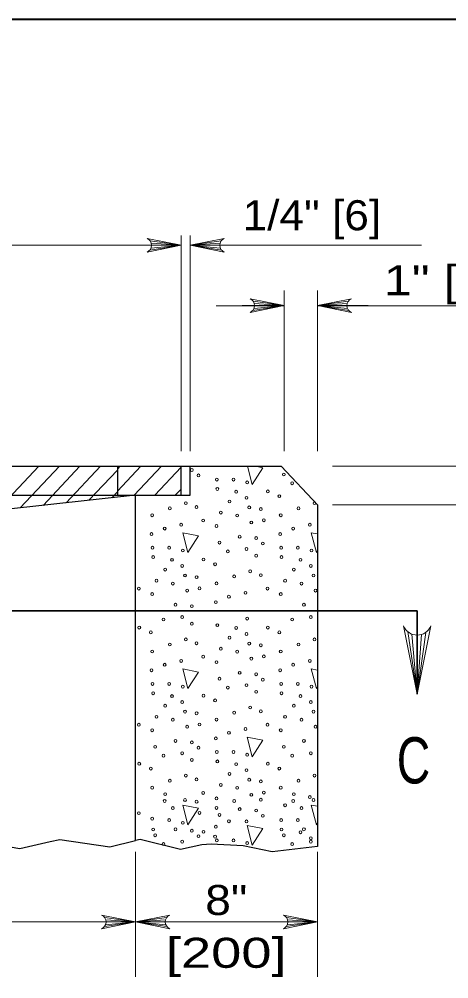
# Model space of a CAD drawing. Extents: x -410.5 to -376.5, y 1617.6 to 1661.6.
# Drawn here: x -402.283 to -400.052, y 1634.082 to 1639.062 of the extents above; entities that cross this region are included whole.
import ezdxf
from ezdxf.enums import TextEntityAlignment as Align

# ---------------------------------------------------------------- set-up
doc = ezdxf.new("R2010")
doc.units = 0
doc.header["$LTSCALE"] = 0.062
doc.layers.add('1', color=7, linetype='Continuous', lineweight=13)

msp = doc.modelspace()

# ---------------------------------------------------------------- linework, layer by layer
at = {"layer": '1', "lineweight": 25}
for p, q in [((-408.45475, 1639.06183), (-376.95475, 1639.06183)), ((-401.77275, 1636.74175), (-401.39508, 1636.74175)), ((-401.44233, 1636.59183), (-401.44233, 1636.74175)), ((-404.3215, 1636.59183), (-401.77275, 1636.59183)), ((-401.67833, 1634.79958), (-401.67833, 1636.59183))]:
    msp.add_line(p, q, dxfattribs=at)
at = {"layer": '1'}
for p, q in [((-401.44233, 1636.82042), (-401.44233, 1637.93875)), ((-401.39508, 1636.82042), (-401.39508, 1637.93875)), ((-401.60442, 1637.864), (-401.44233, 1637.88875)), ((-401.60258, 1637.91117), (-401.44233, 1637.88875)), ((-401.59833, 1637.87442), (-401.44233, 1637.88875)), ((-401.59717, 1637.90008), (-401.44233, 1637.88875)), ((-401.5955, 1637.88875), (-401.44233, 1637.88875)), ((-401.23483, 1637.91117), (-401.39508, 1637.88875)), ((-401.24033, 1637.90008), (-401.39508, 1637.88875)), ((-401.39508, 1637.88875), (-400.19475, 1637.88875)), ((-401.24192, 1637.88875), (-401.39508, 1637.88875)), ((-401.23908, 1637.87442), (-401.39508, 1637.88875)), ((-401.233, 1637.864), (-401.39508, 1637.88875)), ((-400.90758, 1636.82042), (-400.90758, 1637.65358)), ((-400.73433, 1636.82042), (-400.73433, 1637.65358)), ((-400.90758, 1637.57492), (-401.26067, 1637.57492)), ((-400.90758, 1637.57567), (-401.12608, 1637.57567)), ((-401.06975, 1637.55092), (-400.90758, 1637.57567)), ((-401.06783, 1637.59808), (-400.90758, 1637.57567)), ((-401.06358, 1637.56133), (-400.90758, 1637.57567)), ((-401.06242, 1637.587), (-400.90758, 1637.57567)), ((-401.06075, 1637.57567), (-400.90758, 1637.57567)), ((-400.57408, 1637.59808), (-400.73433, 1637.57567)), ((-400.5795, 1637.587), (-400.73433, 1637.57567)), ((-400.73433, 1637.57567), (-400.47133, 1637.57567)), ((-400.58117, 1637.57567), (-400.73433, 1637.57567)), ((-400.57833, 1637.56133), (-400.73433, 1637.57567)), ((-400.57217, 1637.55092), (-400.73433, 1637.57567)), ((-399.40992, 1637.57492), (-400.73433, 1637.57492)), ((-402.39733, 1636.513), (-402.18125, 1636.74175)), ((-402.27817, 1636.52608), (-402.0745, 1636.74175)), ((-402.15908, 1636.53908), (-401.96767, 1636.74175)), ((-402.03983, 1636.55217), (-401.86083, 1636.74175)), ((-401.89075, 1636.74175), (-401.70192, 1636.74175)), ((-401.77275, 1636.61325), (-401.65133, 1636.74167)), ((-401.77275, 1636.72625), (-401.75817, 1636.74167)), ((-401.686, 1636.59192), (-401.54458, 1636.74167)), ((-401.57925, 1636.59192), (-401.44233, 1636.73683)), ((-401.39508, 1636.59183), (-401.39508, 1636.74175)), ((-401.01817, 1636.7345), (-401.05558, 1636.74175)), ((-400.65567, 1636.74175), (-394.85592, 1636.74175)), ((-401.92075, 1636.56525), (-401.77275, 1636.722)), ((-401.80167, 1636.57825), (-401.77275, 1636.60892)), ((-401.74208, 1636.58483), (-401.73542, 1636.59183)), ((-401.6825, 1636.59133), (-401.68208, 1636.59183)), ((-401.47242, 1636.59192), (-401.44233, 1636.62375)), ((-400.65567, 1636.54183), (-400.27733, 1636.54183)), ((-400.65567, 1636.54183), (-394.85592, 1636.54183)), ((-400.73433, 1636.39075), (-400.76633, 1636.39708)), ((-400.26583, 1635.88375), (-400.21625, 1635.5595)), ((-400.24508, 1635.8715), (-400.21625, 1635.5595)), ((-400.17142, 1635.88), (-400.21625, 1635.5595)), ((-400.19358, 1635.86908), (-400.21625, 1635.5595)), ((-400.21625, 1635.86583), (-400.21625, 1635.5595)), ((-400.73442, 1635.68408), (-400.76633, 1635.69033)), ((-400.73433, 1634.9775), (-400.76633, 1634.98367)), ((-401.67833, 1634.09325), (-401.67833, 1634.74117)), ((-400.73433, 1634.09325), (-400.73433, 1634.74117)), ((-401.83858, 1634.40017), (-401.67833, 1634.37775)), ((-401.83317, 1634.38908), (-401.67833, 1634.37775)), ((-401.51808, 1634.40017), (-401.67833, 1634.37775)), ((-401.5235, 1634.38908), (-401.67833, 1634.37775)), ((-400.89458, 1634.40017), (-400.73433, 1634.37775)), ((-400.88917, 1634.38908), (-400.73433, 1634.37775)), ((-402.5235, 1634.37775), (-401.67833, 1634.37775)), ((-401.84042, 1634.353), (-401.67833, 1634.37775)), ((-401.83433, 1634.36333), (-401.67833, 1634.37775)), ((-401.8315, 1634.37775), (-401.67833, 1634.37775)), ((-401.67833, 1634.37775), (-400.96875, 1634.37775)), ((-401.52517, 1634.37775), (-401.67833, 1634.37775)), ((-401.52233, 1634.36333), (-401.67833, 1634.37775)), ((-401.51617, 1634.353), (-401.67833, 1634.37775)), ((-401.02175, 1634.37775), (-400.73433, 1634.37775)), ((-400.89642, 1634.353), (-400.73433, 1634.37775)), ((-400.89033, 1634.36333), (-400.73433, 1634.37775)), ((-400.8875, 1634.37775), (-400.73433, 1634.37775))]:
    msp.add_line(p, q, dxfattribs=at)
at = {"layer": '1', "lineweight": 35}
for p, q in [((-405.888, 1635.99217), (-400.21625, 1635.99217)), ((-400.21625, 1635.99217), (-400.21625, 1635.5595))]:
    msp.add_line(p, q, dxfattribs=at)
at = {"layer": '1', "lineweight": 40}
msp.add_lwpolyline([(-408.45475, 1639.06183), (-376.95475, 1639.06183), (-376.95475, 1618.06183), (-408.45475, 1618.06183)], close=True, dxfattribs=at)
msp.add_lwpolyline([(-408.45475, 1639.06183), (-376.95475, 1639.06183), (-376.95475, 1618.06183), (-408.45475, 1618.06183)], close=True, dxfattribs=at)
at = {"layer": '1'}
for points in [[(-401.61933, 1637.85342), (-401.44233, 1637.88875), (-401.61933, 1637.92417)], [(-401.21808, 1637.85342), (-401.39508, 1637.88875), (-401.21808, 1637.92417)], [(-404.65192, 1637.88875), (-402.994, 1637.88875), (-401.86958, 1637.88875), (-401.44233, 1637.88875)], [(-401.08458, 1637.54033), (-400.90758, 1637.57567), (-401.08458, 1637.61108)], [(-400.55733, 1637.54033), (-400.73433, 1637.57567), (-400.55733, 1637.61108)], [(-401.09775, 1636.74167), (-401.07308, 1636.648), (-401.01817, 1636.7345)], [(-400.76633, 1636.39708), (-400.73933, 1636.29467), (-400.73425, 1636.3025)], [(-400.28708, 1635.9135), (-400.21625, 1635.5595), (-400.1455, 1635.9135)], [(-400.76633, 1635.69033), (-400.73933, 1635.588), (-400.73433, 1635.59583)], [(-400.76633, 1634.98367), (-400.73933, 1634.88117), (-400.73433, 1634.88925)], [(-401.85533, 1634.34233), (-401.67833, 1634.37775), (-401.85533, 1634.41317)], [(-401.50133, 1634.34233), (-401.67833, 1634.37775), (-401.50133, 1634.41317)], [(-400.91133, 1634.34233), (-400.73433, 1634.37775), (-400.91133, 1634.41317)]]:
    msp.add_lwpolyline(points, dxfattribs=at)
at = {"layer": '1', "lineweight": 25}
msp.add_lwpolyline([(-403.04708, 1636.44192), (-404.41592, 1636.59183), (-404.3215, 1636.59183), (-404.3215, 1636.74175), (-401.77275, 1636.74175), (-401.77275, 1636.59183), (-401.67833, 1636.59183)], close=True, dxfattribs=at)
for points in [[(-401.67833, 1636.59183), (-401.39508, 1636.59183), (-401.39508, 1636.74175), (-400.92308, 1636.74175), (-400.73433, 1636.54183), (-400.73433, 1634.76942)], [(-404.41592, 1634.78325), (-404.2725, 1634.75117), (-404.153, 1634.78225), (-403.98442, 1634.76358), (-403.92575, 1634.76642), (-403.82517, 1634.80067), (-403.76458, 1634.79342), (-403.7105, 1634.79125), (-403.49083, 1634.75217), (-403.33433, 1634.80033), (-403.13075, 1634.77958), (-402.962, 1634.81358), (-402.852, 1634.82042), (-402.67125, 1634.76517), (-402.5025, 1634.79617), (-402.27992, 1634.75808), (-402.12158, 1634.79417), (-402.07225, 1634.80517), (-401.81283, 1634.767), (-401.67833, 1634.79958)], [(-400.73433, 1634.76942), (-400.96875, 1634.74142), (-401.11925, 1634.77325), (-401.286, 1634.78183), (-401.33525, 1634.77683), (-401.44525, 1634.75283), (-401.65542, 1634.80508), (-401.67833, 1634.79958)]]:
    msp.add_lwpolyline(points, dxfattribs=at)
at = {"layer": '1'}
for points in [[(-401.43383, 1636.39708), (-401.40683, 1636.29467), (-401.35183, 1636.38108)], [(-401.43383, 1635.69033), (-401.40683, 1635.588), (-401.35183, 1635.67442)], [(-401.1, 1635.337), (-401.07308, 1635.23458), (-401.01817, 1635.321)], [(-401.43383, 1634.98367), (-401.40683, 1634.88117), (-401.35183, 1634.96767)], [(-401.1, 1634.87842), (-401.07308, 1634.77608), (-401.01817, 1634.86258)]]:
    msp.add_lwpolyline(points, close=True, dxfattribs=at)
for centre, radius, start, end in [((-401.63361, 1637.88882), 0.0382, 292.08605, 67.91218), ((-401.20382, 1637.88882), 0.0382, 112.08782, 247.91395), ((-401.09887, 1637.57573), 0.0382, 292.08605, 67.91218), ((-400.54302, 1637.57573), 0.0382, 112.08782, 247.91395), ((-400.2162, 1635.94207), 0.0764, 202.08605, 337.91218), ((-401.86961, 1634.3778), 0.0382, 292.08605, 67.91218), ((-401.48702, 1634.3778), 0.0382, 112.08782, 247.91395), ((-400.92561, 1634.3778), 0.0382, 292.08605, 67.91218)]:
    msp.add_arc(centre, radius, start, end, dxfattribs=at)
for centre, major_axis in [((-401.38687, 1636.72267), (0, 0.00756)), ((-401.35144, 1636.69469), (0, -0.00756)), ((-401.25682, 1636.67273), (0, -0.00756)), ((-401.17027, 1636.67273), (0, 0.00756)), ((-400.90894, 1636.69947), (0, 0.00756)), ((-401.25415, 1636.62408), (0, -0.00756)), ((-401.09912, 1636.65842), (0, -0.00756)), ((-400.86566, 1636.65365), (0, 0.00756)), ((-401.15586, 1636.60977), (0, 0.00756)), ((-401.10274, 1636.57827), (0, 0.00756)), ((-400.99188, 1636.61166), (0, -0.00756)), ((-400.93241, 1636.58686), (0, -0.00756)), ((-401.50046, 1636.52361), (0, -0.00756)), ((-401.41752, 1636.55029), (0, -0.00756)), ((-401.36257, 1636.53027), (0, -0.00756)), ((-401.19107, 1636.55919), (0, 0.00756)), ((-401.08827, 1636.52868), (0, 0.00756)), ((-400.83295, 1636.52361), (0, -0.00756)), ((-400.75001, 1636.55029), (0, -0.00756)), ((-401.59269, 1636.48757), (0, -0.00756)), ((-401.23641, 1636.50165), (0, 0.00756)), ((-401.15141, 1636.48669), (0, 0.00756)), ((-401.02792, 1636.52002), (0, -0.00756)), ((-400.92518, 1636.48757), (0, -0.00756)), ((-401.44189, 1636.43863), (0, -0.00756)), ((-401.32747, 1636.4606), (0, 0.00756)), ((-401.25893, 1636.43198), (0, 0.00756)), ((-401.07754, 1636.45041), (0, 0.00756)), ((-401.01262, 1636.4619), (0, -0.00756)), ((-400.77438, 1636.43863), (0, -0.00756)), ((-401.59597, 1636.38999), (0, -0.00756)), ((-401.52755, 1636.41861), (0, -0.00756)), ((-401.13817, 1636.37668), (0, 0.00756)), ((-400.92846, 1636.38999), (0, -0.00756)), ((-400.86004, 1636.41861), (0, -0.00756)), ((-401.24269, 1636.34612), (0, 0.00756)), ((-401.05312, 1636.36932), (0, 0.00756)), ((-401.01769, 1636.34135), (0, -0.00756)), ((-401.59058, 1636.31938), (0, -0.00756)), ((-401.50402, 1636.31938), (0, 0.00756)), ((-401.43288, 1636.30507), (0, -0.00756)), ((-401.19942, 1636.3003), (0, 0.00756)), ((-401.10302, 1636.31272), (0, 0.00756)), ((-401.05223, 1636.27804), (0, -0.00756)), ((-400.92307, 1636.31938), (0, -0.00756)), ((-400.83651, 1636.31938), (0, 0.00756)), ((-400.76537, 1636.30507), (0, -0.00756)), ((-401.58791, 1636.27073), (0, -0.00756)), ((-401.48961, 1636.25642), (0, 0.00756)), ((-401.43649, 1636.22492), (0, 0.00756)), ((-401.32563, 1636.25831), (0, -0.00756)), ((-401.26617, 1636.23351), (0, -0.00756)), ((-400.9204, 1636.27073), (0, -0.00756)), ((-400.82211, 1636.25642), (0, 0.00756)), ((-400.76898, 1636.22492), (0, 0.00756)), ((-401.52483, 1636.20584), (0, 0.00756)), ((-401.42203, 1636.17533), (0, 0.00756)), ((-401.08377, 1636.19694), (0, -0.00756)), ((-401.02881, 1636.17692), (0, -0.00756)), ((-400.85732, 1636.20584), (0, 0.00756)), ((-400.75452, 1636.17533), (0, 0.00756)), ((-401.57016, 1636.1483), (0, 0.00756)), ((-401.48516, 1636.13334), (0, 0.00756)), ((-401.36168, 1636.16667), (0, -0.00756)), ((-401.25893, 1636.13422), (0, -0.00756)), ((-401.16671, 1636.17026), (0, -0.00756)), ((-400.90265, 1636.1483), (0, 0.00756)), ((-400.81766, 1636.13334), (0, 0.00756)), ((-401.66122, 1636.10725), (0, 0.00756)), ((-401.59269, 1636.07863), (0, 0.00756)), ((-401.41129, 1636.09706), (0, 0.00756)), ((-401.34638, 1636.10855), (0, -0.00756)), ((-401.10813, 1636.08528), (0, -0.00756)), ((-400.99371, 1636.10725), (0, 0.00756)), ((-400.92518, 1636.07863), (0, 0.00756)), ((-400.74378, 1636.09706), (0, 0.00756)), ((-401.47193, 1636.02333), (0, 0.00756)), ((-401.26222, 1636.03664), (0, -0.00756)), ((-401.1938, 1636.06526), (0, -0.00756)), ((-400.80442, 1636.02333), (0, 0.00756)), ((-401.38687, 1636.01597), (0, 0.00756)), ((-401.53317, 1635.94695), (0, 0.00756)), ((-401.43677, 1635.95937), (0, 0.00756)), ((-401.38598, 1635.92469), (0, -0.00756)), ((-401.09912, 1635.95172), (0, -0.00756)), ((-400.86566, 1635.94695), (0, 0.00756)), ((-400.76926, 1635.95937), (0, 0.00756)), ((-401.65938, 1635.90496), (0, -0.00756)), ((-401.59992, 1635.88016), (0, -0.00756)), ((-401.25415, 1635.91738), (0, -0.00756)), ((-401.15586, 1635.90307), (0, 0.00756)), ((-400.99188, 1635.90496), (0, -0.00756)), ((-400.93241, 1635.88016), (0, -0.00756)), ((-401.41752, 1635.84359), (0, -0.00756)), ((-401.19107, 1635.85249), (0, 0.00756)), ((-401.10274, 1635.87157), (0, 0.00756)), ((-400.75001, 1635.84359), (0, -0.00756)), ((-401.59269, 1635.78087), (0, -0.00756)), ((-401.50046, 1635.81692), (0, -0.00756)), ((-401.36257, 1635.82357), (0, -0.00756)), ((-401.23641, 1635.79495), (0, 0.00756)), ((-401.15141, 1635.77999), (0, 0.00756)), ((-401.08827, 1635.82198), (0, 0.00756)), ((-401.02792, 1635.81332), (0, -0.00756)), ((-400.92518, 1635.78087), (0, -0.00756)), ((-400.83295, 1635.81692), (0, -0.00756)), ((-401.44189, 1635.73193), (0, -0.00756)), ((-401.32747, 1635.7539), (0, 0.00756)), ((-401.25893, 1635.72528), (0, 0.00756)), ((-401.07754, 1635.74371), (0, 0.00756)), ((-401.01262, 1635.7552), (0, -0.00756)), ((-400.77438, 1635.73193), (0, -0.00756)), ((-401.59597, 1635.68329), (0, -0.00756)), ((-401.52755, 1635.71191), (0, -0.00756)), ((-400.92846, 1635.68329), (0, -0.00756)), ((-400.86004, 1635.71191), (0, -0.00756)), ((-401.24269, 1635.63942), (0, 0.00756)), ((-401.13817, 1635.66998), (0, 0.00756)), ((-401.05312, 1635.66262), (0, 0.00756)), ((-401.01769, 1635.63465), (0, -0.00756)), ((-401.59058, 1635.61268), (0, -0.00756)), ((-401.50402, 1635.61268), (0, 0.00756)), ((-401.43288, 1635.59837), (0, -0.00756)), ((-401.19942, 1635.5936), (0, 0.00756)), ((-401.10302, 1635.60602), (0, 0.00756)), ((-400.92307, 1635.61268), (0, -0.00756)), ((-400.83651, 1635.61268), (0, 0.00756)), ((-400.76537, 1635.59837), (0, -0.00756)), ((-401.58791, 1635.56403), (0, -0.00756)), ((-401.48961, 1635.54972), (0, 0.00756)), ((-401.32563, 1635.55161), (0, -0.00756)), ((-401.26617, 1635.52681), (0, -0.00756)), ((-401.05223, 1635.57134), (0, -0.00756)), ((-400.9204, 1635.56403), (0, -0.00756)), ((-400.82211, 1635.54972), (0, 0.00756)), ((-401.52483, 1635.49914), (0, 0.00756)), ((-401.43649, 1635.51822), (0, 0.00756)), ((-401.08377, 1635.49024), (0, -0.00756)), ((-400.85732, 1635.49914), (0, 0.00756)), ((-400.76898, 1635.51822), (0, 0.00756)), ((-401.57016, 1635.4416), (0, 0.00756)), ((-401.48516, 1635.42664), (0, 0.00756)), ((-401.42203, 1635.46863), (0, 0.00756)), ((-401.36168, 1635.45997), (0, -0.00756)), ((-401.25893, 1635.42752), (0, -0.00756)), ((-401.16671, 1635.46357), (0, -0.00756)), ((-401.02881, 1635.47022), (0, -0.00756)), ((-400.90265, 1635.4416), (0, 0.00756)), ((-400.81766, 1635.42664), (0, 0.00756)), ((-400.75452, 1635.46863), (0, 0.00756)), ((-401.66122, 1635.40055), (0, 0.00756)), ((-401.41129, 1635.39036), (0, 0.00756)), ((-401.34638, 1635.40185), (0, -0.00756)), ((-401.10813, 1635.37858), (0, -0.00756)), ((-400.99371, 1635.40055), (0, 0.00756)), ((-400.74378, 1635.39036), (0, 0.00756)), ((-401.59269, 1635.37193), (0, 0.00756)), ((-401.26222, 1635.32994), (0, -0.00756)), ((-401.1938, 1635.35856), (0, -0.00756)), ((-400.92518, 1635.37193), (0, 0.00756)), ((-401.57645, 1635.28607), (0, 0.00756)), ((-401.47193, 1635.31663), (0, 0.00756)), ((-401.38687, 1635.30927), (0, 0.00756)), ((-401.35144, 1635.2813), (0, -0.00756)), ((-400.90894, 1635.28607), (0, 0.00756)), ((-400.80442, 1635.31663), (0, 0.00756)), ((-401.53317, 1635.24025), (0, 0.00756)), ((-401.43677, 1635.25267), (0, 0.00756)), ((-401.25682, 1635.25933), (0, -0.00756)), ((-401.17027, 1635.25933), (0, 0.00756)), ((-401.09912, 1635.24502), (0, -0.00756)), ((-400.86566, 1635.24025), (0, 0.00756)), ((-400.76926, 1635.25267), (0, 0.00756)), ((-401.65938, 1635.19826), (0, -0.00756)), ((-401.38598, 1635.21799), (0, -0.00756)), ((-401.25415, 1635.21068), (0, -0.00756)), ((-401.15586, 1635.19637), (0, 0.00756)), ((-400.99188, 1635.19826), (0, -0.00756)), ((-401.59992, 1635.17347), (0, -0.00756)), ((-401.41752, 1635.13689), (0, -0.00756)), ((-401.19107, 1635.14579), (0, 0.00756)), ((-401.10274, 1635.16487), (0, 0.00756)), ((-400.93241, 1635.17347), (0, -0.00756)), ((-400.75001, 1635.13689), (0, -0.00756)), ((-401.50046, 1635.11022), (0, -0.00756)), ((-401.36257, 1635.11687), (0, -0.00756)), ((-401.23641, 1635.08825), (0, 0.00756)), ((-401.08827, 1635.11528), (0, 0.00756)), ((-401.02792, 1635.10662), (0, -0.00756)), ((-400.83295, 1635.11022), (0, -0.00756)), ((-401.59269, 1635.07417), (0, -0.00756)), ((-401.52483, 1635.04062), (0, 0.00756)), ((-401.32747, 1635.0472), (0, 0.00756)), ((-401.15141, 1635.07329), (0, 0.00756)), ((-401.07754, 1635.03701), (0, 0.00756)), ((-401.01262, 1635.0485), (0, -0.00756)), ((-400.92518, 1635.07417), (0, -0.00756)), ((-400.85732, 1635.04062), (0, 0.00756)), ((-401.52755, 1635.00521), (0, -0.00756)), ((-401.42203, 1635.01012), (0, 0.00756)), ((-401.36168, 1635.00146), (0, -0.00756)), ((-401.25893, 1635.01858), (0, 0.00756)), ((-401.16671, 1635.00505), (0, -0.00756)), ((-401.02881, 1635.01171), (0, -0.00756)), ((-400.90265, 1634.98308), (0, 0.00756)), ((-400.86004, 1635.00521), (0, -0.00756)), ((-400.77438, 1635.02523), (0, -0.00756)), ((-400.75452, 1635.01012), (0, 0.00756)), ((-401.66122, 1634.94204), (0, 0.00756)), ((-401.48516, 1634.96813), (0, 0.00756)), ((-401.34638, 1634.94333), (0, -0.00756)), ((-401.25894, 1634.96901), (0, -0.00756)), ((-401.24269, 1634.93272), (0, 0.00756)), ((-401.13817, 1634.96328), (0, 0.00756)), ((-401.05312, 1634.95592), (0, 0.00756)), ((-401.01769, 1634.92795), (0, -0.00756)), ((-400.81766, 1634.96813), (0, 0.00756)), ((-401.59269, 1634.91342), (0, 0.00756)), ((-401.50402, 1634.90598), (0, 0.00756)), ((-401.43288, 1634.89167), (0, -0.00756)), ((-401.1938, 1634.90005), (0, -0.00756)), ((-401.10302, 1634.89932), (0, 0.00756)), ((-400.92307, 1634.90598), (0, -0.00756)), ((-400.83651, 1634.90598), (0, 0.00756)), ((-401.58791, 1634.85733), (0, -0.00756)), ((-401.47193, 1634.85812), (0, 0.00756)), ((-401.38687, 1634.85075), (0, 0.00756)), ((-401.32563, 1634.84491), (0, -0.00756)), ((-401.26222, 1634.87143), (0, -0.00756)), ((-400.9204, 1634.85733), (0, -0.00756)), ((-400.82211, 1634.84302), (0, 0.00756)), ((-400.80442, 1634.85812), (0, 0.00756)), ((-401.57645, 1634.82755), (0, 0.00756)), ((-401.53317, 1634.78173), (0, 0.00756)), ((-401.43677, 1634.79416), (0, 0.00756)), ((-401.35144, 1634.82278), (0, -0.00756)), ((-401.26617, 1634.82012), (0, -0.00756)), ((-401.25682, 1634.80081), (0, -0.00756)), ((-401.17027, 1634.80081), (0, 0.00756)), ((-401.09912, 1634.7865), (0, -0.00756)), ((-400.90894, 1634.82755), (0, 0.00756)), ((-400.86566, 1634.78173), (0, 0.00756)), ((-400.76926, 1634.79416), (0, 0.00756)), ((-400.76898, 1634.81152), (0, 0.00756))]:
    msp.add_ellipse(centre, major_axis=major_axis, ratio=0.944543, dxfattribs=at)

# ---------------------------------------------------------------- texts
for s, width, p in [('1/4" [6]', 1.1, (-401.12292, 1637.96658)), ('1" [25]', 1.25, (-400.38933, 1637.62858))]:
    msp.add_text(s, height=0.156, dxfattribs=dict(at, width=width)).set_placement(p)
for s, height, width, p in [('C', 0.24, 0.75, (-400.23558, 1635.09608)), ('8"', 0.156, 1.15, (-401.20792, 1634.41342)), ('[200]', 0.156, 1.35, (-401.20792, 1634.13942))]:
    msp.add_text(s, height=height, dxfattribs=dict(at, width=width)).set_placement(p, align=Align.CENTER)

doc.saveas('drawing.dxf')
